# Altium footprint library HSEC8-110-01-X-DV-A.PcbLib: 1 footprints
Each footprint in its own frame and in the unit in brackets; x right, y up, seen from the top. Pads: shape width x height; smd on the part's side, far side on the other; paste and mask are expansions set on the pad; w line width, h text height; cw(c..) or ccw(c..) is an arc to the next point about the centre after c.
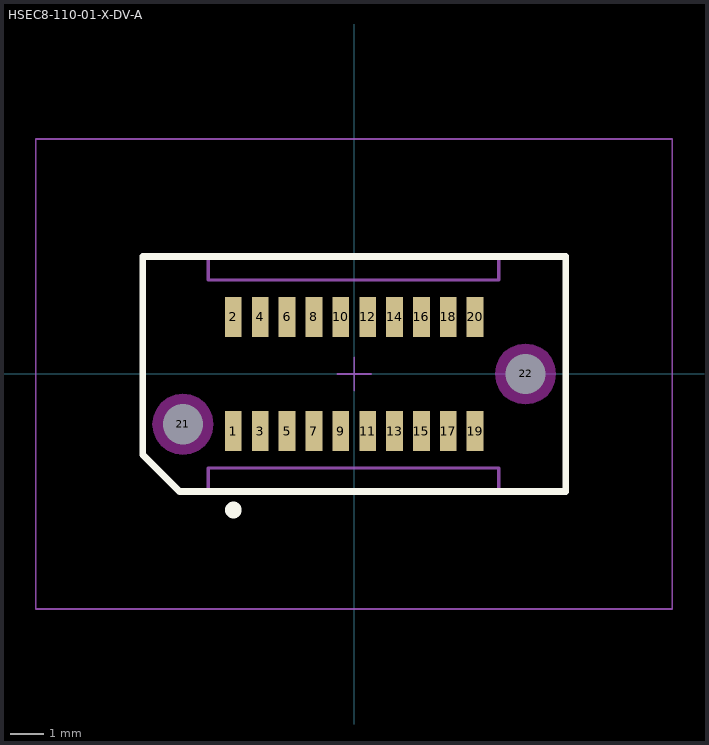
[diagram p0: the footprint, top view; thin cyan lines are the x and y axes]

## HSEC8-110-01-X-DV-A [mm] "0.80mm pitch, 20 pin, hi-speed micro edge card; w/alignment pins"
height 7.98
pads (22):
  rect 0.5x1.2 smd mask+0: 1(-3.6,-1.7) 2(-3.6,1.7) 3(-2.8,-1.7) 4(-2.8,1.7) 5(-2,-1.7) 6(-2,1.7) 7(-1.2,-1.7) 8(-1.2,1.7) 9(-0.4,-1.7) 10(-0.4,1.7) 11(0.4,-1.7) 12(0.4,1.7) 13(1.2,-1.7) 14(1.2,1.7) 15(2,-1.7) 16(2,1.7) 17(2.8,-1.7) 18(2.8,1.7) 19(3.6,-1.7) 20(3.6,1.7)
  round 0.5 hole 1.2 unplated mask+0: 21(-5.1,-1.5) 22(5.1,0)
Top Overlay:
  circle w0.25: c-3.6,-4.05 r0.125
  lines w0.2: -6.3,-2.4 -5.2,-3.5 6.3,-3.5 6.3,3.5 -6.3,3.5 -6.3,-2.4
Keep-Out Layer:
  pour cut-out: -4.192,-1.5 -4.223,-1.265 -4.314,-1.046 -4.458,-0.858 -4.646,-0.714 -4.865,-0.623 -5.1,-0.592 -5.335,-0.623 -5.554,-0.714 -5.742,-0.858 -5.886,-1.046 -5.977,-1.265 -6.008,-1.5 -5.977,-1.735 -5.886,-1.954 -5.742,-2.142 -5.554,-2.286 -5.335,-2.377 -5.1,-2.408 -4.865,-2.377 -4.646,-2.286 -4.458,-2.142 -4.314,-1.954 -4.223,-1.735
  pour cut-out: 6.008,0 5.977,0.235 5.886,0.454 5.742,0.642 5.554,0.786 5.335,0.877 5.1,0.908 4.865,0.877 4.646,0.786 4.458,0.642 4.314,0.454 4.223,0.235 4.192,0 4.223,-0.235 4.314,-0.454 4.458,-0.642 4.646,-0.786 4.865,-0.877 5.1,-0.908 5.335,-0.877 5.554,-0.786 5.742,-0.642 5.886,-0.454 5.977,-0.235
Mechanical 12:
  lines w0.001: -6.3,-2.4 -5.2,-3.5 6.3,-3.5 6.3,3.5 -6.3,3.5 -6.3,-2.4
Mechanical 13:
  lines w0.1: -6.3,-2.4 -5.2,-3.5 -4.35,-3.5 -4.35,-2.8 4.3,-2.8 4.3,-3.5 6.3,-3.5 6.3,3.5 4.3,3.5 4.3,2.8 -4.35,2.8 -4.35,3.5 -6.3,3.5 -6.3,-2.4
  text ".Designator" at 0.254,0.254 h1.52
Mechanical 15:
  lines w0.05: -0.5,0 0.5,0 ; 0,-0.5 0,0.5 ; -9.481,-7 9.467,-7 9.467,7 -9.481,7 -9.481,-7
